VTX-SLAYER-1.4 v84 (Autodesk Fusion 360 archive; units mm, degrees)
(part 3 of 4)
sketch "vtx-antenna_mount" plane through (0, 0, 32) normal (0, 0, -1) x axis (1, 0, 0)
  line L1 (-21.0607, 19.5622) -> (-27.6022, 26.6869)
  curve K1 (-9.6778, 20.9358) -> (-10.9746, 20.0338)
  curve K2 (21.4163, 20.9358) -> (22.7131, 20.0338)
  line L2 (34.4732, 21.3854) -> (32.7992, 19.5622)
  curve K3 (34.4732, 21.3854) -> (34.8613, 29.5821)
  curve K4 (34.4729, 47.5027) -> (34.8613, 50.4161)
  curve K5 (34.8613, 50.4161) -> (34.4732, 58.6128)
  line L3 (32.7992, 60.4361) -> (34.4732, 58.6128)
  curve K6 (21.4163, 59.0625) -> (22.7131, 59.9644)
  curve K7 (-9.6778, 59.0625) -> (-10.9746, 59.9644)
  line L4 (-27.6022, 53.3114) -> (-21.0607, 60.4361)
  line L5 (26.3392, 29.4991) -> (30.319, 29.4991)
  line L6 (30.319, 32.4991) -> (26.3392, 32.4991)
  line L7 (30.319, 50.4991) -> (26.3392, 50.4991)
  line L8 (26.3392, 47.4991) -> (30.319, 47.4991)
  line L9 (30.319, 29.4991) -> (26.3392, 29.4991)
  line L10 (26.3392, 32.4991) -> (30.319, 32.4991)
  line L11 (30.319, 47.4991) -> (26.3392, 47.4991)
  line L12 (26.3392, 50.4991) -> (30.319, 50.4991)
  curve K8 (34.47, 47.4768) -> (31.9524, 44.1894)
  curve K9 (34.4729, 47.5027) -> (34.8613, 50.4161)
  curve K10 (34.8613, 50.4161) -> (34.4732, 58.6128)
  line L13 (34.4732, 58.6128) -> (32.7992, 60.4361)
  curve K11 (22.7131, 59.9644) -> (21.4163, 59.0625)
  curve K12 (34.4732, 21.3854) -> (34.8613, 29.5821)
  line L14 (32.7992, 19.5622) -> (34.4732, 21.3854)
  curve K13 (21.4163, 20.9358) -> (22.7131, 20.0338)
  line L15 (19.3693, 59.1611) -> (19.3693, 25.3947)
  line L16 (42, 39.9991) -> (17.9297, 39.9991)
  line L17 (34.47, 32.5215) -> (34.47, 47.4768)
  line L18 (34.47, 47.4768) -> (34.6901, 56.5235)
  line L19 (34.47, 32.5215) -> (34.6901, 23.4747)
  curve K14 (5.8693, 25.0204) -> (-1.6863, 24.3869)
  curve K15 (5.8693, 54.9778) -> (-1.6863, 55.6114)
  curve K16 (-13.7829, 18.3445) -> (-21.0607, 19.5622)
  curve K17 (-10.9746, 20.0338) -> (-13.7829, 18.3445)
  curve K18 (5.8693, 25.0204) -> (13.4249, 24.3869)
  curve K19 (22.7131, 20.0338) -> (25.5215, 18.3445)
  curve K20 (32.7992, 19.5622) -> (25.5215, 18.3445)
  curve K21 (32.7992, 60.4361) -> (25.5215, 61.6537)
  curve K22 (22.7131, 59.9644) -> (25.5215, 61.6537)
  curve K23 (5.8693, 54.9778) -> (13.4249, 55.6114)
  curve K24 (-10.9746, 59.9644) -> (-13.7829, 61.6537)
  curve K25 (-13.7829, 61.6537) -> (-21.0607, 60.4361)
  curve K26 (-13.7829, 18.3445) -> (-10.9746, 20.0338)
  curve K27 (25.5215, 18.3445) -> (32.7992, 19.5622)
  curve K28 (-9.4692, 21.0728) -> (-9.6778, 20.9358)
  curve K29 (-1.6863, 24.3869) -> (-1.7709, 24.37)
  curve K30 (13.4249, 24.3869) -> (13.5094, 24.37)
  curve K31 (21.2077, 21.0728) -> (21.4163, 20.9358)
  curve K32 (21.2077, 58.9255) -> (21.4163, 59.0625)
  curve K33 (13.4249, 55.6114) -> (13.5094, 55.6283)
  curve K34 (-1.6863, 55.6114) -> (-1.7709, 55.6283)
  curve K35 (-9.4692, 58.9255) -> (-9.6778, 59.0625)
  curve K36 (34.4729, 32.4955) -> (34.8613, 29.5821)
  curve K37 (34.47, 32.5215) -> (31.9524, 35.8089)
  line L20 (24.7082, 44.5019) -> (21.9057, 47.2714)
  line L21 (26.1937, 39.0527) -> (26.1937, 40.9455)
  line L22 (21.9057, 32.7269) -> (24.7082, 35.4963)
  line L23 (2.0745, 29.0204) -> (9.5861, 29.0204)
  line L24 (9.5861, 50.9778) -> (2.0745, 50.9778)
  curve K38 (-1.7709, 24.37) -> (-9.4692, 21.0728)
  curve K39 (13.5094, 24.37) -> (21.2077, 21.0728)
  line L25 (34.4729, 32.4955) -> (34.47, 32.5215)
  line L26 (34.47, 47.4768) -> (34.4729, 47.5027)
  curve K40 (13.5094, 55.6283) -> (21.2077, 58.9255)
  curve K41 (-1.7709, 55.6283) -> (-9.4692, 58.9255)
  line L27 (-9.3955, 28.8599) -> (-15.7249, 35.138)
  line L28 (10.9945, 32.4404) -> (7.2082, 36.196)
  line L29 (4.3798, 36.1845) -> (0.6546, 32.4289)
  line L30 (7.2082, 43.8022) -> (10.9945, 47.5578)
  line L31 (0.6546, 47.5694) -> (4.3798, 43.8137)
  line L32 (-3.666, 33.753) -> (-0.2646, 37.1822)
  line L33 (-12.0826, 37.1592) -> (-8.5664, 33.6715)
  line L34 (-8.5664, 46.3268) -> (-12.0826, 42.839)
  line L35 (-0.2646, 42.816) -> (-3.666, 46.2452)
  line L36 (15.3511, 46.2451) -> (11.9172, 42.839)
  line L37 (11.9172, 37.1592) -> (15.3511, 33.7531)
  line L38 (-15.7249, 44.8602) -> (-9.3955, 51.1383)
  arc A1 centre (-25.3924, 51.2824) radius 3 clockwise from (-26.8824, 48.6786) to (-27.6022, 53.3114)
  arc A2 centre (-31.849, 39.9991) radius 10 clockwise from (-26.8824, 48.6786) to (-26.8824, 31.3197)
  arc A3 centre (-25.3924, 28.7158) radius 3 clockwise from (-27.6022, 26.6869) to (-26.8824, 31.3197)
  circle C1 centre (-18.1307, 23.4991) radius 1.55
  circle C2 centre (-18.1307, 56.4991) radius 1.55
  arc A4 centre (26.3392, 30.9991) radius 1.5 clockwise from (26.3392, 29.4991) to (26.3392, 32.4991)
  arc A5 centre (30.319, 30.9991) radius 1.5 clockwise from (30.319, 32.4991) to (30.319, 29.4991)
  arc A6 centre (30.319, 48.9991) radius 1.5 clockwise from (30.319, 50.4991) to (30.319, 47.4991)
  arc A7 centre (26.3392, 48.9991) radius 1.5 clockwise from (26.3392, 47.4991) to (26.3392, 50.4991)
  arc A8 centre (26.3392, 30.9991) radius 1.5 clockwise from (26.3392, 29.4991) to (26.3392, 32.4991)
  arc A9 centre (30.319, 30.9991) radius 1.5 clockwise from (30.319, 32.4991) to (30.319, 29.4991)
  arc A10 centre (26.3392, 48.9991) radius 1.5 clockwise from (26.3392, 47.4991) to (26.3392, 50.4991)
  arc A11 centre (30.319, 48.9991) radius 1.5 clockwise from (30.319, 50.4991) to (30.319, 47.4991)
  arc A12 centre (33.5931, 39.9991) radius 4.5 clockwise from (31.9524, 35.8089) to (31.9524, 44.1894)
  circle C3 centre (29.8693, 56.4991) radius 4.8209
  circle C4 centre (29.8693, 56.4991) radius 3.025
  circle C5 centre (29.8693, 23.4991) radius 4.8209
  circle C6 centre (29.8693, 23.4991) radius 3.025
  arc A13 centre (50.9984, 39.9992) radius 31.6291 clockwise from (26.0429, 20.5666) to (26.0525, 59.4441)
  circle C7 centre (29.8693, 56.4991) radius 1.55
  circle C8 centre (29.8693, 23.4991) radius 1.55
  circle C9 centre (15.8693, 49.9991) radius 1.05
  circle C10 centre (-4.1307, 49.9991) radius 1.05
  circle C11 centre (15.8693, 29.9991) radius 1.05
  circle C12 centre (-4.1307, 29.9991) radius 1.05
  arc A14 centre (15.8693, 29.9991) radius 3.25 clockwise from (16.4204, 33.202) to (17.9117, 32.5272)
  arc A15 centre (-4.1307, 29.9991) radius 3.25 clockwise from (-5.3387, 33.0163) to (-4.7221, 33.1949)
  arc A16 centre (-18.1307, 23.4991) radius 5.55 clockwise from (-18.4728, 29.0386) to (-13.5782, 26.6736)
  arc A17 centre (-31.849, 39.9991) radius 14 clockwise from (-18.9728, 34.5032) to (-20.2526, 32.1553)
  arc A18 centre (-18.1307, 56.4991) radius 5.55 clockwise from (-13.5782, 53.3246) to (-18.4728, 50.9597)
  arc A19 centre (-4.1307, 49.9991) radius 3.25 clockwise from (-4.7221, 46.8034) to (-5.3387, 46.9819)
  arc A20 centre (15.8693, 49.9991) radius 3.25 clockwise from (17.9117, 47.4711) to (16.4204, 46.7962)
  arc A21 centre (-10.8039, 27.4399) radius 2 clockwise from (-9.3955, 28.8599) to (-10.177, 25.5408)
  arc A22 centre (-11.1174, 28.3895) radius 3 clockwise from (-10.177, 25.5408) to (-13.5782, 26.6736)
  arc A23 centre (-18.596, 31.0348) radius 2 clockwise from (-18.4728, 29.0386) to (-20.2526, 32.1553)
  arc A24 centre (-17.1334, 33.7181) radius 2 clockwise from (-18.9728, 34.5032) to (-15.7249, 35.138)
  arc A25 centre (9.5861, 31.0204) radius 2 clockwise from (10.9945, 32.4404) to (9.5861, 29.0204)
  arc A26 centre (2.0745, 31.0204) radius 2 clockwise from (2.0745, 29.0204) to (0.6546, 32.4289)
  arc A27 centre (5.7998, 34.7761) radius 2 clockwise from (4.3798, 36.1845) to (7.2082, 36.196)
  arc A28 centre (2.0745, 48.9778) radius 2 clockwise from (0.6546, 47.5694) to (2.0745, 50.9778)
  arc A29 centre (9.5861, 48.9778) radius 2 clockwise from (9.5861, 50.9778) to (10.9945, 47.5578)
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  point P53 (34.47, 47.4768)
  point P68 (34.47, 47.4768)
  point P71 (34.6901, 56.5235)
  point P72 (34.47, 47.4768)
  point P75 (34.6901, 23.4747)
  point P76 (34.47, 32.5215)
  point P78 (26.0429, 20.5666)
  point P77 (26.0525, 59.4441)
  perpendicular L15 L16
  coincident P53 P68
  tangent L3 C3
  coincident C3 P71
  coincident P53 P72
  symmetric L16 C3 C5
  symmetric L16 C4 C6
  symmetric L16 P71 P75
  symmetric L16 P72 P76
  tangent L15 A13
  coincident C5 P78
  coincident C3 P77
  dimension "d1057" diameter C4 = 6.05
sketch "turtleFinBase" plane through (0, 0, 33.5) normal (0, 0, 1) x axis (-1, 0, 0)
  line L1 (21.0607, 60.4361) -> (27.6022, 53.3114)
  curve K1 (13.7829, 61.6537) -> (21.0607, 60.4361)
  curve K2 (10.9746, 59.9644) -> (13.7829, 61.6537)
  curve K3 (9.6778, 59.0625) -> (10.9746, 59.9644)
  curve K4 (9.4692, 58.9255) -> (9.6778, 59.0625)
  curve K5 (1.7709, 55.6283) -> (9.4692, 58.9255)
  curve K6 (1.6863, 55.6114) -> (1.7709, 55.6283)
  curve K7 (-5.8693, 54.9778) -> (1.6863, 55.6114)
  curve K8 (-13.4249, 55.6114) -> (-5.8693, 54.9778)
  curve K9 (-13.5094, 55.6283) -> (-13.4249, 55.6114)
  curve K10 (-21.2077, 58.9255) -> (-13.5094, 55.6283)
  curve K11 (-21.4163, 59.0625) -> (-21.2077, 58.9255)
  curve K12 (-22.7131, 59.9644) -> (-21.4163, 59.0625)
  curve K13 (-25.5215, 61.6537) -> (-22.7131, 59.9644)
  curve K14 (-32.7992, 60.4361) -> (-25.5215, 61.6537)
  line L2 (-34.4732, 58.6128) -> (-32.7992, 60.4361)
  curve K15 (-34.8613, 50.4161) -> (-34.4732, 58.6128)
  curve K16 (-34.4729, 47.5027) -> (-34.8613, 50.4161)
  line L3 (-34.47, 47.4768) -> (-34.4729, 47.5027)
  curve K17 (-34.47, 47.4768) -> (-31.9524, 44.1894)
  curve K18 (-31.9524, 35.8089) -> (-34.47, 32.5215)
  line L4 (-34.4729, 32.4955) -> (-34.47, 32.5215)
  curve K19 (-34.8613, 29.5821) -> (-34.4729, 32.4955)
  curve K20 (-34.4732, 21.3854) -> (-34.8613, 29.5821)
  line L5 (-32.7992, 19.5622) -> (-34.4732, 21.3854)
  curve K21 (-25.5215, 18.3445) -> (-32.7992, 19.5622)
  curve K22 (-22.7131, 20.0338) -> (-25.5215, 18.3445)
  curve K23 (-21.4163, 20.9358) -> (-22.7131, 20.0338)
  curve K24 (-21.2077, 21.0728) -> (-21.4163, 20.9358)
  curve K25 (-13.5094, 24.37) -> (-21.2077, 21.0728)
  curve K26 (-13.4249, 24.3869) -> (-13.5094, 24.37)
  curve K27 (-5.8693, 25.0204) -> (-13.4249, 24.3869)
  curve K28 (1.6863, 24.3869) -> (-5.8693, 25.0204)
  curve K29 (1.7709, 24.37) -> (1.6863, 24.3869)
  curve K30 (9.4692, 21.0728) -> (1.7709, 24.37)
  curve K31 (9.6778, 20.9358) -> (9.4692, 21.0728)
  curve K32 (10.9746, 20.0338) -> (9.6778, 20.9358)
  curve K33 (13.7829, 18.3445) -> (10.9746, 20.0338)
  curve K34 (21.0607, 19.5622) -> (13.7829, 18.3445)
  line L6 (27.6022, 26.6869) -> (21.0607, 19.5622)
  line L7 (-15.3511, 33.7531) -> (-11.9172, 37.1592)
  line L8 (-24.7082, 35.4963) -> (-21.9057, 32.7269)
  line L9 (-26.1937, 40.9455) -> (-26.1937, 39.0527)
  line L10 (-21.9057, 47.2714) -> (-24.7082, 44.5019)
  line L11 (-11.9172, 42.839) -> (-15.3511, 46.2451)
  line L12 (-30.319, 29.4991) -> (-26.3392, 29.4991)
  line L13 (-26.3392, 32.4991) -> (-30.319, 32.4991)
  line L14 (-26.3392, 50.4991) -> (-30.319, 50.4991)
  line L15 (-30.319, 47.4991) -> (-26.3392, 47.4991)
  line L16 (-2.0745, 50.9778) -> (-9.5861, 50.9778)
  line L17 (-4.3798, 43.8137) -> (-0.6546, 47.5694)
  line L18 (-10.9945, 47.5578) -> (-7.2082, 43.8022)
  line L19 (15.7249, 35.138) -> (9.3955, 28.8599)
  line L20 (3.666, 46.2452) -> (0.2646, 42.816)
  line L21 (12.0826, 42.839) -> (8.5664, 46.3268)
  line L22 (8.5664, 33.6715) -> (12.0826, 37.1592)
  line L23 (0.2646, 37.1822) -> (3.666, 33.753)
  line L24 (-0.6546, 32.4289) -> (-4.3798, 36.1845)
  line L25 (-9.5861, 29.0204) -> (-2.0745, 29.0204)
  line L26 (-7.2082, 36.196) -> (-10.9945, 32.4404)
  line L27 (9.3955, 51.1383) -> (15.7249, 44.8602)
  line L28 (10.424, 50.6687) -> (18.7336, 51.7161)
  line L29 (8.6626, 58.4333) -> (16.6107, 61.0741)
  line L30 (-20.4518, 21.7537) -> (-28.2425, 18.961)
  line L31 (-22.3854, 29.4762) -> (-30.5729, 28.2684)
  arc A1 centre (25.3924, 51.2824) radius 3 clockwise from (27.6022, 53.3114) to (26.8824, 48.6786)
  arc A2 centre (-33.5931, 39.9991) radius 4.5 clockwise from (-31.9524, 44.1894) to (-31.9524, 35.8089)
  arc A3 centre (25.3924, 28.7158) radius 3 clockwise from (26.8824, 31.3197) to (27.6022, 26.6869)
  arc A4 centre (31.849, 39.9991) radius 10 clockwise from (26.8824, 31.3197) to (26.8824, 48.6786)
  circle C1 centre (-29.8693, 23.4991) radius 1.55
  arc A5 centre (-16.7595, 35.1731) radius 2 clockwise from (-15.3511, 33.7531) to (-16.4204, 33.202)
  arc A6 centre (-15.8693, 29.9991) radius 3.25 clockwise from (-17.9117, 32.5272) to (-16.4204, 33.202)
  arc A7 centre (-19.797, 34.8608) radius 3 clockwise from (-17.9117, 32.5272) to (-21.9057, 32.7269)
  arc A8 centre (-21.1937, 39.0527) radius 5 clockwise from (-24.7082, 35.4963) to (-26.1937, 39.0527)
  arc A9 centre (-21.1937, 40.9455) radius 5 clockwise from (-26.1937, 40.9455) to (-24.7082, 44.5019)
  arc A10 centre (-19.797, 45.1375) radius 3 clockwise from (-21.9057, 47.2714) to (-17.9117, 47.4711)
  arc A11 centre (-15.8693, 49.9991) radius 3.25 clockwise from (-16.4204, 46.7962) to (-17.9117, 47.4711)
  arc A12 centre (-16.7595, 44.8252) radius 2 clockwise from (-16.4204, 46.7962) to (-15.3511, 46.2451)
  arc A13 centre (-14.7341, 39.9991) radius 4 clockwise from (-11.9172, 42.839) to (-11.9172, 37.1592)
  arc A14 centre (-26.3392, 30.9991) radius 1.5 clockwise from (-26.3392, 32.4991) to (-26.3392, 29.4991)
  arc A15 centre (-30.319, 30.9991) radius 1.5 clockwise from (-30.319, 29.4991) to (-30.319, 32.4991)
  circle C2 centre (4.1307, 29.9991) radius 1.05
  circle C3 centre (18.1307, 56.4991) radius 1.55
  circle C4 centre (-15.8693, 49.9991) radius 1.05
  circle C5 centre (18.1307, 23.4991) radius 1.55
  arc A16 centre (-30.319, 48.9991) radius 1.5 clockwise from (-30.319, 47.4991) to (-30.319, 50.4991)
  arc A17 centre (-26.3392, 48.9991) radius 1.5 clockwise from (-26.3392, 50.4991) to (-26.3392, 47.4991)
  circle C6 centre (-29.8693, 56.4991) radius 1.55
  circle C7 centre (-15.8693, 29.9991) radius 1.05
  circle C8 centre (4.1307, 49.9991) radius 1.05
  arc A18 centre (-2.0745, 48.9778) radius 2 clockwise from (-2.0745, 50.9778) to (-0.6546, 47.5694)
  arc A19 centre (-5.7998, 45.2221) radius 2 clockwise from (-4.3798, 43.8137) to (-7.2082, 43.8022)
  arc A20 centre (-9.5861, 48.9778) radius 2 clockwise from (-10.9945, 47.5578) to (-9.5861, 50.9778)
  arc A21 centre (31.849, 39.9991) radius 14 clockwise from (20.2526, 32.1553) to (18.9728, 34.5032)
  arc A22 centre (18.596, 31.0348) radius 2 clockwise from (20.2526, 32.1553) to (18.4728, 29.0386)
  arc A23 centre (18.1307, 23.4991) radius 5.55 clockwise from (13.5782, 26.6736) to (18.4728, 29.0386)
  arc A24 centre (11.1174, 28.3895) radius 3 clockwise from (13.5782, 26.6736) to (10.177, 25.5408)
  arc A25 centre (10.8039, 27.4399) radius 2 clockwise from (10.177, 25.5408) to (9.3955, 28.8599)
  arc A26 centre (17.1334, 33.7181) radius 2 clockwise from (15.7249, 35.138) to (18.9728, 34.5032)
  arc A27 centre (5.0859, 44.8367) radius 2 clockwise from (3.666, 46.2452) to (4.7221, 46.8034)
  arc A28 centre (4.1307, 49.9991) radius 3.25 clockwise from (5.3387, 46.9819) to (4.7221, 46.8034)
  arc A29 centre (6.4537, 44.1968) radius 3 clockwise from (5.3387, 46.9819) to (8.5664, 46.3268)
  arc A30 centre (9.2657, 39.9991) radius 4 clockwise from (12.0826, 42.839) to (12.0826, 37.1592)
  arc A31 centre (6.4537, 35.8014) radius 3 clockwise from (8.5664, 33.6715) to (5.3387, 33.0163)
  arc A32 centre (4.1307, 29.9991) radius 3.25 clockwise from (4.7221, 33.1949) to (5.3387, 33.0163)
  arc A33 centre (5.0859, 35.1615) radius 2 clockwise from (4.7221, 33.1949) to (3.666, 33.753)
  arc A34 centre (3.1045, 39.9991) radius 4 clockwise from (0.2646, 37.1822) to (0.2646, 42.816)
  arc A35 centre (-2.0745, 31.0204) radius 2 clockwise from (-0.6546, 32.4289) to (-2.0745, 29.0204)
  arc A36 centre (-9.5861, 31.0204) radius 2 clockwise from (-9.5861, 29.0204) to (-10.9945, 32.4404)
  arc A37 centre (-5.7998, 34.7761) radius 2 clockwise from (-7.2082, 36.196) to (-4.3798, 36.1845)
  arc A38 centre (31.849, 39.9991) radius 14 clockwise from (18.9728, 45.495) to (20.2526, 47.8429)
  arc A39 centre (17.1334, 46.2801) radius 2 clockwise from (18.9728, 45.495) to (15.7249, 44.8602)
  arc A40 centre (10.8039, 52.5583) radius 2 clockwise from (9.3955, 51.1383) to (10.177, 54.4575)
  arc A41 centre (11.1174, 51.6087) radius 3 clockwise from (10.177, 54.4575) to (13.5782, 53.3246)
  arc A42 centre (18.1307, 56.4991) radius 5.55 clockwise from (18.4728, 50.9597) to (13.5782, 53.3246)
  arc A43 centre (18.596, 48.9635) radius 2 clockwise from (18.4728, 50.9597) to (20.2526, 47.8429)
  circle C9 centre (18.1307, 56.4991) radius 4.8209
  circle C10 centre (-29.8693, 23.4991) radius 4.8209
  circle C11 centre (-21.8016, 25.519) radius 4
  circle C12 centre (9.9238, 54.6373) radius 4
  point P153 (18.7336, 51.7161)
  point P154 (10.424, 50.6687)
  point P155 (16.6107, 61.0741)
  point P156 (8.6626, 58.4333)
  point P157 (-28.2425, 18.961)
  point P158 (-20.4518, 21.7537)
  point P159 (-30.5729, 28.2684)
  point P160 (-22.3854, 29.4762)
  concentric C3 C9
  tangent L1 C9
  concentric C1 C10
  tangent L5 C10
  coincident C9 P153
  coincident C12 P154
  tangent C12 L28
  coincident C9 P155
  coincident C12 P156
  tangent C12 L29
  coincident C10 P157
  coincident C11 P158
  tangent C11 L30
  coincident C10 P159
  coincident C11 P160
  tangent C11 L31
  tangent C9 L29
  tangent C9 L28
  tangent C10 L31
  tangent C10 L30
  dimension "d1172" diameter C11 = 8
  dimension "d1173" diameter C12 = 8
extrude "Extrude141" new body sketch "turtleFinBase" profile of C1 C3 L27 A40 A41 A42 C9 C10 C11 C12 L28 L29 L30 L31 along normal blind 3 bodies "turtleFin"
sketch "Sketch97" plane through (0, 0, 36.5) normal (0, 0, 1) x axis (-1, 0, 0)
  line L1 (8.6626, 58.4333) -> (16.6107, 61.0741)
  line L2 (18.7336, 51.7161) -> (10.424, 50.6687)
  circle C1 centre (18.1307, 56.4991) radius 1.55
  arc A1 centre (18.1307, 56.4991) radius 4.8209 clockwise from (16.6107, 61.0741) to (18.7336, 51.7161)
  arc A2 centre (9.9238, 54.6373) radius 4 clockwise from (10.424, 50.6687) to (8.6626, 58.4333)
  circle C2 centre (9.9238, 54.6373) radius 4
work_plane "WorkPlane19"
sketch "Sketch98" plane through (-9.9238, -54.6373, 33.5) normal (-0.6762, 0.7367, 0) x axis (-0.7367, -0.6762, 0)
  line L1 (-43, 3) -> (0, 3)
  line L2 (-21.5, 38) -> (-21.5, 3)
  line L3 (-4, 0) -> (4, 0)
  line L4 (-47.0624, 0) -> (-39.0624, 0)
  curve K1 (-39.0624, 0) -> (-4, 0)
  curve K2 (-43.0624, 0) -> (0, 0)
  point P4 (-21.5, 3)
  point P7 (-4, 0)
  point P10 (-4, 0)
  point P11 (-21.5, 35.2015)
  point P8 (-39.0624, 0)
  point P12 (-39.0624, 0)
  point P1 (0, 0)
  point P13 (0, 0)
  point P14 (-43.0624, 0)
  point P5 (-21.5, 38)
  horizontal L1
  midpoint L1 P4
  perpendicular L1 L2
  coincident P7 P10
  coincident L2 P11
  coincident P8 P12
  coincident P1 P13
  midpoint L4 P14
  dimension "d1176" distance P4 P5 = 35
sweep "Sweep1" sketch "turtleFinBase" TwistAngle 0 TaperAngle 0
fillet "Fillet113" radius 3
work_plane "WorkPlane15" RotateAngle -45
sketch "vtx-antenna-hole" plane through (20.4594, -39.9991, 30.9099) normal (0.7071, 0, 0.7071) x axis (0, -1, 0)
  line L1 (0, 25) -> (0, -3.5)
  circle C1 centre (0, 11.4101) radius 4.5
  circle C2 centre (0, 11.4101) radius 2.5
  concentric C1 C2
  vertical L1
  dimension "d882" diameter C1 = 9
  dimension "d883" diameter C2 = 5
extrude "Extrude127" new body sketch "vtx-antenna-hole" profile of C1 C2 along normal blind 25 bodies "vtx-antenna-mount"
extrude "Extrude128" add sketch "vtx-antenna_mount" along normal blind 3
extrude "Extrude129" cut sketch "vtx-antenna-hole" profile of C2 along normal blind 47
work_plane "WorkPlane18" RotateAngle -90
sketch "Sketch92" plane through (19.3693, -39.9991, 29) normal (1, 0, 0) x axis (0, 1, 0)
  line L1 (-6.5, 0) -> (6.5, 0)
  line L2 (-6.5, -10.2079) -> (-6.5, 0)
  line L3 (6.5, -10.2079) -> (-6.5, -10.2079)
  line L4 (6.5, 0) -> (6.5, -10.2079)
  line L5 (-8.0736, 0) -> (-19.445, 0)
  line L6 (19.4325, 0) -> (8.0736, 0)
  horizontal L1
  vertical L2
  horizontal L3
  vertical L4
extrude "Extrude130" cut sketch "Sketch92" profile of L1 L2 L3 L4 along normal blind 29
fillet "Fillet99" radius 0.8
fillet "Fillet100" radius 4
fillet "Fillet101" radius 0.7
fillet "Fillet108" radius 3
fillet "Fillet109" radius 7
sketch "Sketch93" plane through (0, 0, 29) normal (0, 0, -1) x axis (1, 0, 0)
  line L1 (26.3392, 47.4991) -> (30.319, 47.4991)
  line L2 (30.319, 50.4991) -> (26.3392, 50.4991)
  line L3 (34.47, 47.4768) -> (34.47, 47.2361)
  line L4 (34.4729, 47.5027) -> (34.47, 47.4768)
  curve K1 (34.8613, 50.4161) -> (34.4729, 47.5027)
  curve K2 (34.4732, 58.6128) -> (34.8613, 50.4161)
  line L5 (33.4204, 59.7595) -> (34.4732, 58.6128)
  line L6 (24.7082, 44.5019) -> (23.7608, 45.4381)
  line L7 (26.1937, 39.0527) -> (26.1937, 40.9455)
  line L8 (23.7609, 34.5602) -> (24.7082, 35.4963)
  line L9 (34.4732, 21.3854) -> (33.4204, 20.2387)
  curve K3 (34.8613, 29.5821) -> (34.4732, 21.3854)
  curve K4 (34.4729, 32.4955) -> (34.8613, 29.5821)
  line L10 (34.47, 32.5215) -> (34.4729, 32.4955)
  line L11 (34.47, 32.7621) -> (34.47, 32.5215)
  line L12 (26.3392, 29.4991) -> (30.319, 29.4991)
  line L13 (30.319, 32.4991) -> (26.3392, 32.4991)
  curve K5 (34.47, 32.7621) -> (36.774, 35.7482)
  curve K6 (36.774, 44.25) -> (34.47, 47.2361)
  arc A1 centre (29.8693, 56.4991) radius 4.8209 clockwise from (26.0525, 59.4441) to (33.4204, 59.7595)
  arc A2 centre (19.5063, 39.9991) radius 7.6719 clockwise from (20.3034, 47.6295) to (20.3035, 32.3688)
  closed curve K7 centre (35.4859, 39.9991)
  arc A3 centre (30.319, 48.9991) radius 1.5 clockwise from (30.319, 50.4991) to (30.319, 47.4991)
  arc A4 centre (26.3392, 48.9991) radius 1.5 clockwise from (26.3392, 47.4991) to (26.3392, 50.4991)
  circle C1 centre (29.8693, 56.4991) radius 3.025
  arc A5 centre (50.9984, 39.9992) radius 31.6291 clockwise from (26.0429, 20.5666) to (22.3382, 26.6202)
  arc A6 centre (21.1937, 40.9455) radius 5 clockwise from (24.7082, 44.5019) to (26.1937, 40.9455)
  arc A7 centre (21.1937, 39.0527) radius 5 clockwise from (26.1937, 39.0527) to (24.7082, 35.4963)
  arc A8 centre (29.8693, 23.4991) radius 4.8209 clockwise from (33.4204, 20.2387) to (26.0429, 20.5666)
  closed curve K8 centre (34.6859, 39.9991)
  circle C2 centre (29.8693, 23.4991) radius 3.025
  arc A9 centre (30.319, 30.9991) radius 1.5 clockwise from (30.319, 32.4991) to (30.319, 29.4991)
  arc A10 centre (26.3392, 30.9991) radius 1.5 clockwise from (26.3392, 29.4991) to (26.3392, 32.4991)
  arc A11 centre (28.6812, 29.5812) radius 7 clockwise from (22.3382, 26.6202) to (23.7609, 34.5602)
  arc A12 centre (50.9984, 39.9992) radius 31.6291 clockwise from (22.3382, 53.3781) to (26.0525, 59.4441)
  arc A13 centre (28.6811, 50.4171) radius 7 clockwise from (23.7608, 45.4381) to (22.3382, 53.3781)
sketch "25.6 mount" plane through (0, 0, 7) normal (0, 0, 1) x axis (-1, 0, 0)
  curve K1 (2.0117, 48.6726) -> (-5.8693, 49.9885)
  curve K2 (11.053, 39.9991) -> (5.0002, 47.6552)
  curve K3 (5.0002, 32.3431) -> (11.053, 39.9991)
  curve K4 (-5.8693, 30.0098) -> (2.0117, 31.3257)
  curve K5 (-13.7502, 31.3257) -> (-5.8693, 30.0098)
  curve K6 (-15.8119, 47.4998) -> (-15.9266, 32.4985)
  curve K7 (-5.8693, 49.9885) -> (-13.7502, 48.6726)
  curve K8 (-34.4732, 21.3854) -> (-34.8613, 29.5821)
  line L1 (-32.7992, 19.5622) -> (-34.4732, 21.3854)
  curve K9 (-32.7992, 19.5622) -> (-25.5215, 18.3445)
  curve K10 (-22.7131, 20.0338) -> (-25.5215, 18.3445)
  curve K11 (-21.4163, 20.9358) -> (-22.7131, 20.0338)
  curve K12 (-21.2077, 21.0728) -> (-21.4163, 20.9358)
  curve K13 (-13.5094, 24.37) -> (-21.2077, 21.0728)
  curve K14 (-13.4249, 24.3869) -> (-13.5094, 24.37)
  curve K15 (-5.8693, 25.0204) -> (-13.4249, 24.3869)
  curve K16 (-5.8693, 25.0204) -> (1.6863, 24.3869)
  curve K17 (1.6863, 24.3869) -> (1.7709, 24.37)
  curve K18 (9.4692, 21.0728) -> (1.7709, 24.37)
  curve K19 (9.4692, 21.0728) -> (9.6778, 20.9358)
  curve K20 (9.6778, 20.9358) -> (10.9746, 20.0338)
  curve K21 (10.9746, 20.0338) -> (13.7829, 18.3445)
  curve K22 (13.7829, 18.3445) -> (21.0607, 19.5622)
  line L2 (21.7601, 20.324) -> (21.0607, 19.5622)
  curve K23 (23.3399, 24.4614) -> (21.2218, 28.4813)
  curve K24 (14.991, 38.4401) -> (21.2218, 28.4813)
  curve K25 (14.9178, 39.9991) -> (14.991, 38.4401)
  curve K26 (14.9178, 39.9991) -> (14.991, 41.5582)
  curve K27 (14.991, 41.5582) -> (21.2218, 51.5169)
  curve K28 (21.2218, 51.5169) -> (23.3399, 55.5369)
  line L3 (21.0607, 60.4361) -> (21.7601, 59.6743)
  curve K29 (13.7829, 61.6537) -> (21.0607, 60.4361)
  curve K30 (10.9746, 59.9644) -> (13.7829, 61.6537)
  curve K31 (9.6778, 59.0625) -> (10.9746, 59.9644)
  curve K32 (9.4692, 58.9255) -> (9.6778, 59.0625)
  curve K33 (1.7709, 55.6283) -> (9.4692, 58.9255)
  curve K34 (1.6863, 55.6114) -> (1.7709, 55.6283)
  curve K35 (-5.8693, 54.9778) -> (1.6863, 55.6114)
  curve K36 (-5.8693, 54.9778) -> (-13.4249, 55.6114)
  curve K37 (-13.4249, 55.6114) -> (-13.5094, 55.6283)
  curve K38 (-21.2077, 58.9255) -> (-13.5094, 55.6283)
  curve K39 (-21.2077, 58.9255) -> (-21.4163, 59.0625)
  curve K40 (-21.4163, 59.0625) -> (-22.7131, 59.9644)
  curve K41 (-22.7131, 59.9644) -> (-25.5215, 61.6537)
  curve K42 (-32.7992, 60.4361) -> (-25.5215, 61.6537)
  line L4 (-34.4732, 58.6128) -> (-32.7992, 60.4361)
  curve K43 (-34.8613, 50.4161) -> (-34.4732, 58.6128)
  curve K44 (-34.4729, 47.5027) -> (-34.8613, 50.4161)
  curve K45 (-34.2161, 44.4991) -> (-34.4729, 47.5027)
  curve K46 (-34.0919, 41.4991) -> (-34.2161, 44.4991)
  curve K47 (-34.0692, 39.9991) -> (-34.0919, 41.4991)
  curve K48 (-34.0919, 38.4991) -> (-34.0692, 39.9991)
  curve K49 (-34.0919, 38.4991) -> (-34.2161, 35.4991)
  curve K50 (-34.4729, 32.4955) -> (-34.2161, 35.4991)
  curve K51 (-34.4729, 32.4955) -> (-34.8613, 29.5821)
  line L5 (-26.3392, 32.4991) -> (-30.319, 32.4991)
  line L6 (-30.319, 29.4991) -> (-26.3392, 29.4991)
  line L7 (-23.7522, 38.4991) -> (-30.319, 38.4991)
  line L8 (-30.319, 35.4991) -> (-23.7522, 35.4991)
  line L9 (-26.3392, 50.4991) -> (-30.319, 50.4991)
  line L10 (-30.319, 47.4991) -> (-26.3392, 47.4991)
  line L11 (-23.7522, 44.4991) -> (-30.319, 44.4991)
  line L12 (-30.319, 41.4991) -> (-23.7522, 41.4991)
  line L13 (-15.8693, 49.9991) -> (4.1307, 29.9991)
  line L14 (-15.8693, 29.9991) -> (4.1307, 49.9991)
  line L15 (-5.8693, 9.9991) -> (-5.8693, 39.9991)
  line L16 (-35.8693, 39.9991) -> (-5.8693, 39.9991)
  line L17 (-5.8693, 69.9991) -> (-5.8693, 39.9991)
  line L18 (24.1307, 39.9991) -> (-5.8693, 39.9991)
  line L19 (-23.9712, 39.9991) -> (-5.8693, 58.1011)
  line L20 (-5.8693, 21.8972) -> (-23.9712, 39.9991)
  line L21 (-5.8693, 21.8972) -> (12.2327, 39.9991)
  line L22 (0.3923, 24.6107) -> (-4.104, 20.127)
  line L23 (-12.109, 24.6139) -> (-7.6395, 20.1319)
  line L24 (0.3923, 55.3876) -> (-4.104, 59.8713)
  line L25 (-12.109, 55.3843) -> (-7.6395, 59.8663)
  arc A1 centre (4.1307, 49.9991) radius 2.5 clockwise from (5.0002, 47.6552) to (2.0117, 48.6726)
  arc A2 centre (4.1307, 29.9991) radius 2.5 clockwise from (2.0117, 31.3257) to (5.0002, 32.3431)
  arc A3 centre (-15.8693, 29.9991) radius 2.5 clockwise from (-15.9266, 32.4985) to (-13.7502, 31.3257)
  arc A4 centre (-15.8693, 49.9991) radius 2.5 clockwise from (-13.7502, 48.6726) to (-15.8119, 47.4998)
  arc A5 centre (17.3404, 24.3819) radius 6 clockwise from (23.3399, 24.4614) to (21.7601, 20.324)
  arc A6 centre (17.3404, 55.6164) radius 6 clockwise from (21.7601, 59.6743) to (23.3399, 55.5369)
  arc A7 centre (-30.319, 30.9991) radius 1.5 clockwise from (-30.319, 29.4991) to (-30.319, 32.4991)
  arc A8 centre (-26.3392, 30.9991) radius 1.5 clockwise from (-26.3392, 32.4991) to (-26.3392, 29.4991)
  arc A9 centre (-23.7522, 36.9991) radius 1.5 clockwise from (-23.7522, 38.4991) to (-23.7522, 35.4991)
  arc A10 centre (-30.319, 36.9991) radius 1.5 clockwise from (-30.319, 35.4991) to (-30.319, 38.4991)
  arc A11 centre (-26.3392, 48.9991) radius 1.5 clockwise from (-26.3392, 50.4991) to (-26.3392, 47.4991)
  arc A12 centre (-30.319, 48.9991) radius 1.5 clockwise from (-30.319, 47.4991) to (-30.319, 50.4991)
  circle C1 centre (-29.8693, 56.4991) radius 2.55
  circle C2 centre (18.1307, 56.4991) radius 2.55
  circle C3 centre (-29.8693, 23.4991) radius 2.55
  circle C4 centre (18.1307, 23.4991) radius 2.55
  circle C5 centre (4.1307, 49.9991) radius 1.05
  circle C6 centre (-15.8693, 49.9991) radius 1.05
  circle C7 centre (4.1307, 29.9991) radius 1.05
  circle C8 centre (-15.8693, 29.9991) radius 1.05
  arc A13 centre (-30.319, 42.9991) radius 1.5 clockwise from (-30.319, 41.4991) to (-30.319, 44.4991)
  arc A14 centre (-23.7522, 42.9991) radius 1.5 clockwise from (-23.7522, 44.4991) to (-23.7522, 41.4991)
  circle C9 centre (-5.8693, 21.8972) radius 1.05
  circle C10 centre (-5.8693, 58.1011) radius 1.05
  circle C11 centre (12.2327, 39.9991) radius 1.05
  circle C12 centre (-23.9712, 39.9991) radius 1.05
  circle C13 centre (-5.8693, 21.8972) radius 2.5
  circle C14 centre (-5.8693, 58.1011) radius 2.5
  circle C15 centre (12.2327, 39.9991) radius 4
  circle C16 centre (-23.9712, 39.9991) radius 4
  circle C17 centre (-28.581, 42.9991) radius 1.5
  circle C18 centre (-28.581, 36.9991) radius 1.5
  point P9 (4.1307, 29.9991)
  point P97 (4.1307, 29.9991)
  point P16 (-15.8693, 49.9991)
  point P98 (-15.8693, 49.9991)
  point P5 (4.1307, 49.9991)
  point P99 (4.1307, 49.9991)
  point P13 (-15.8693, 29.9991)
  point P100 (-15.8693, 29.9991)
  point P101 (-5.8693, 39.9991)
  point P106 (-5.8693, 21.8972)
  point P107 (-5.8693, 58.1011)
  point P108 (12.2327, 39.9991)
  point P109 (-23.9712, 39.9991)
  point P110 (-5.8693, 58.1011)
  point P111 (-23.9712, 39.9991)
  point P112 (-23.9712, 39.9991)
  point P113 (-5.8693, 21.8972)
  point P114 (12.2327, 39.9991)
  point P115 (-5.8693, 21.8972)
  point P118 (-23.9712, 39.9991)
  point P121 (-4.104, 20.127)
  point P122 (0.3923, 24.6107)
  point P123 (-7.6395, 20.1319)
  point P124 (-12.109, 24.6139)
  point P125 (-4.104, 59.8713)
  point P126 (0.3923, 55.3876)
  point P127 (-7.6395, 59.8663)
  point P128 (-12.109, 55.3843)
  point P119 (-28.581, 42.9991)
  point P120 (-28.581, 36.9991)
  coincident P9 P97
  coincident P16 P98
  coincident P5 P99
  coincident P13 P100
  midpoint L14 P101
  vertical L15
  perpendicular L15 L16
  perpendicular L16 L17
  perpendicular L15 L18
  coincident L15 P106
  coincident L17 P107
  coincident L18 P108
  coincident L16 P109
  coincident P107 P110
  coincident P109 P111
  coincident P109 P112
  coincident P106 P113
  coincident P108 P114
  coincident P113 P115
  concentric C10 C14
  concentric C11 C15
  coincident P111 P118
  tangent L11 C17
  tangent L8 C18
  coincident C13 P121
  coincident K16 P122
  tangent C13 L22
  coincident C13 P123
  coincident K15 P124
  tangent C13 L23
  perpendicular L22 L23
  symmetric L16 P121 P125
  symmetric L16 P122 P126
  symmetric L16 P123 P127
  symmetric L16 P124 P128
  tangent L7 C18
  tangent L12 C17
  vertical P119 P120
  tangent C16 C18
  dimension "d1130" diameter C9 = 2.1
  dimension "d1131" diameter C10 = 2.1
  dimension "d1132" diameter C11 = 2.1
  dimension "d1133" diameter C12 = 2.1
  dimension "d1138" distance P107 P109 = 25.6
  dimension "d1139" angle L17 L19 = 45
  dimension "d1140" distance P106 P109 = 25.6
  dimension "d1141" distance P113 P114 = 25.6
  dimension "d1142" diameter C13 = 5
  dimension "d1143" diameter C14 = 5
  dimension "d1144" diameter C15 = 8
  dimension "d1145" diameter C16 = 8
extrude "Extrude133" cut sketch "25.6 mount" profile of C11 C12 against normal blind 6
extrude "Extrude134" add sketch "25.6 mount" profile of K2 K3 K15 K16 K24 K25 K26 K27 K35 K36 L7 A9 L8 L11 A14 L12 C9 C10 C13 C14 C15 C16 C17 C18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 against normal blind 2
extrude "Extrude135" cut sketch "25.6 mount" profile of C11 C12 against normal blind 2
fillet "Fillet110" radius 3
extrude "Extrude136" cut sketch "25.6 mount" profile of C11 C12 against normal blind 12
sketch "Sketch95" plane through (0, 0, -2) normal (0, 0, -1) x axis (1, 0, 0)
  curve K1 (32.9603, 51.5169) -> (35.0785, 55.5369)
  line L1 (32.7992, 60.4361) -> (33.4986, 59.6743)
  curve K2 (32.7992, 60.4361) -> (25.5215, 61.6537)
  curve K3 (22.7131, 59.9644) -> (25.5215, 61.6537)
  curve K4 (21.4163, 59.0625) -> (22.7131, 59.9644)
  curve K5 (13.5094, 55.6283) -> (21.4163, 59.0625)
  curve K6 (13.4249, 55.6114) -> (13.5094, 55.6283)
  curve K7 (5.8693, 54.9778) -> (13.4249, 55.6114)
  curve K8 (-1.6863, 55.6114) -> (5.8693, 54.9778)
  curve K9 (-1.7709, 55.6283) -> (-1.6863, 55.6114)
  curve K10 (-9.6778, 59.0625) -> (-1.7709, 55.6283)
  curve K11 (-10.9746, 59.9644) -> (-9.6778, 59.0625)
  curve K12 (-13.7829, 61.6537) -> (-10.9746, 59.9644)
  curve K13 (-13.7829, 61.6537) -> (-21.0607, 60.4361)
  line L2 (-32.5504, 47.922) -> (-21.0607, 60.4361)
  line L3 (-34.1307, 36.1341) -> (-34.1307, 43.8641)
  line L4 (-21.0607, 19.5622) -> (-32.5504, 32.0762)
  curve K14 (-13.7829, 18.3445) -> (-21.0607, 19.5622)
  curve K15 (-13.7829, 18.3445) -> (-10.9746, 20.0338)
  curve K16 (-10.9746, 20.0338) -> (-9.6778, 20.9358)
  curve K17 (-9.6778, 20.9358) -> (-1.7709, 24.37)
  curve K18 (-1.7709, 24.37) -> (-1.6863, 24.3869)
  curve K19 (-1.6863, 24.3869) -> (5.8693, 25.0204)
  curve K20 (5.8693, 25.0204) -> (13.4249, 24.3869)
  curve K21 (13.4249, 24.3869) -> (13.5094, 24.37)
  curve K22 (13.5094, 24.37) -> (21.4163, 20.9358)
  curve K23 (21.4163, 20.9358) -> (22.7131, 20.0338)
  curve K24 (22.7131, 20.0338) -> (25.5215, 18.3445)
  curve K25 (32.7992, 19.5622) -> (25.5215, 18.3445)
  line L5 (33.4986, 20.324) -> (32.7992, 19.5622)
  curve K26 (35.0785, 24.4614) -> (32.9603, 28.4813)
  curve K27 (32.9603, 28.4813) -> (26.7295, 38.4401)
  curve K28 (26.7295, 38.4401) -> (26.6564, 39.9991)
  curve K29 (26.7295, 41.5582) -> (26.6564, 39.9991)
  curve K30 (32.9603, 51.5169) -> (26.7295, 41.5582)
  line L6 (-14.6007, 32.4991) -> (-25.1307, 32.4991)
  line L7 (-25.1307, 29.4991) -> (-14.6007, 29.4991)
  line L8 (-29.6307, 35.4991) -> (-12.0137, 35.4991)
  line L9 (-12.0137, 38.4991) -> (-29.6307, 38.4991)
  line L10 (-12.0137, 44.4991) -> (-29.6307, 44.4991)
  line L11 (-29.6307, 41.4991) -> (-12.0137, 41.4991)
  line L12 (-25.1307, 47.4991) -> (-14.6007, 47.4991)
  line L13 (-14.6007, 50.4991) -> (-25.1307, 50.4991)
  circle C1 centre (23.9712, 39.9991) radius 1.05
  circle C2 centre (-12.2327, 39.9991) radius 1.05
  arc A1 centre (29.079, 55.6164) radius 6 clockwise from (33.4986, 59.6743) to (35.0785, 55.5369)
  arc A2 centre (-28.1307, 43.8641) radius 6 clockwise from (-34.1307, 43.8641) to (-32.5504, 47.922)
  arc A3 centre (-28.1307, 36.1341) radius 6 clockwise from (-32.5504, 32.0762) to (-34.1307, 36.1341)
  arc A4 centre (29.079, 24.3819) radius 6 clockwise from (35.0785, 24.4614) to (33.4986, 20.324)
  circle C3 centre (29.8693, 23.4991) radius 1.55
  arc A5 centre (15.8693, 29.9991) radius 2.1 clockwise from (15.8711, 32.0991) to (15.8711, 27.8991)
  arc A6 centre (15.873, 29.9991) radius 2.1 clockwise from (15.8711, 27.8991) to (15.8711, 32.0991)
  circle C4 centre (-4.1307, 29.9991) radius 2.1
  circle C5 centre (-18.1307, 23.4991) radius 1.55
  arc A7 centre (-14.6007, 30.9991) radius 1.5 clockwise from (-14.6007, 32.4991) to (-14.6007, 29.4991)
  arc A8 centre (-25.1307, 30.9991) radius 1.5 clockwise from (-25.1307, 29.4991) to (-25.1307, 32.4991)
  arc A9 centre (-29.6307, 36.9991) radius 1.5 clockwise from (-29.6307, 35.4991) to (-29.6307, 38.4991)
  arc A10 centre (-12.0137, 36.9991) radius 1.5 clockwise from (-12.0137, 38.4991) to (-12.0137, 35.4991)
  circle C6 centre (5.8693, 39.9991) radius 3
  arc A11 centre (-12.0137, 42.9991) radius 1.5 clockwise from (-12.0137, 44.4991) to (-12.0137, 41.4991)
  arc A12 centre (-29.6307, 42.9991) radius 1.5 clockwise from (-29.6307, 41.4991) to (-29.6307, 44.4991)
  arc A13 centre (-25.1307, 48.9991) radius 1.5 clockwise from (-25.1307, 47.4991) to (-25.1307, 50.4991)
  arc A14 centre (-14.6007, 48.9991) radius 1.5 clockwise from (-14.6007, 50.4991) to (-14.6007, 47.4991)
  circle C7 centre (-18.1307, 56.4991) radius 1.55
  circle C8 centre (-4.1307, 49.9991) radius 2.1
  arc A15 centre (15.8693, 49.9991) radius 2.1 clockwise from (15.8711, 52.0991) to (15.8711, 47.8991)
  arc A16 centre (15.873, 49.9991) radius 2.1 clockwise from (15.8711, 47.8991) to (15.8711, 52.0991)
  circle C9 centre (29.8693, 56.4991) radius 1.55
  circle C10 centre (-12.2327, 39.9991) radius 2.1
  circle C11 centre (23.9712, 39.9991) radius 2.1
  circle C12 centre (-12.2327, 39.9991) radius 4
  circle C13 centre (23.9712, 39.9991) radius 4
  circle C14 centre (-16.8424, 42.9991) radius 1.5
  circle C15 centre (-16.8424, 36.9991) radius 1.5
  concentric C2 C10
  concentric C1 C11
  concentric C2 C12
  concentric C11 C13
  tangent L10 C14
  tangent L11 C14
  tangent C12 C14
  tangent L9 C15
  tangent L8 C15
  tangent C12 C15
  dimension "d1156" diameter C10 = 4.2
  dimension "d1157" diameter C11 = 4.2
  dimension "d1158" diameter C12 = 8
  dimension "d1159" diameter C13 = 8
extrude "Extrude137" add sketch "Sketch95" profile of K27 K28 K29 K30 L8 L9 A10 L10 A11 L11 C10 C12 C13 C14 C15 against normal blind 2
extrude "Extrude138" cut sketch "Sketch95" profile of C1 C2 L9 A10 A11 L11 C10 C11 against normal blind 2
fillet "Fillet111" radius 3
extrude "Extrude139" add sketch "25.6 mount" profile of K2 K3 K24 K25 K26 K27 L7 A9 A14 L12 C11 C12 C15 C16 against normal blind 4
extrude "Extrude140" cut sketch "25.6 mount" profile of K2 K3 K24 K25 K26 K27 L7 A9 A14 L12 C11 C12 C15 C16 against normal blind 2
fillet "Fillet112" radius 3
component_insert "Component Insert5"
component_insert "Component Insert6"
extrude "Extrude132" new body sketch "cam-mount-base" profile of C2 C4 along normal blind 25 bodies "standoff1", "standoff2"
copy_paste_bodies "CopyPasteBodies13"
move "Move24"
component_insert "Component Insert7"
joint "Assemble6" alignAngle 0 alignOffsetX 0 alignOffsetY 0 alignOffsetZ 0
component_insert "Component Insert8"
component_insert "Component Insert9"
component_insert "Component Insert10"
joint "Assemble9" alignAngle 0 alignOffsetX 0 alignOffsetY 0 alignOffsetZ 0
component_insert "Component Insert11"
component_insert "Component Insert12"
component_insert "Component Insert13"
component_insert "Component Insert14"
component_insert "Component Insert15"
joint "Assemble14" alignAngle 0 alignOffsetX 0 alignOffsetY 0 alignOffsetZ 0
component_insert "Component Insert16"
component_insert "Component Insert17"
component_insert "Component Insert18"
joint "Assemble15" alignAngle 0 alignOffsetX 0 alignOffsetY 0 alignOffsetZ 0
joint "Assemble16" alignAngle 0 alignOffsetX 0 alignOffsetY 0 alignOffsetZ 0
joint "Assemble17" alignAngle 0 alignOffsetX 0 alignOffsetY 0 alignOffsetZ 0
component_insert "Component Insert19"
component_insert "Component Insert20"
joint "Assemble18" alignAngle 0 alignOffsetX 0 alignOffsetY 0 alignOffsetZ 0
joint "Assemble19" alignAngle 0 alignOffsetX 0 alignOffsetY 0 alignOffsetZ 0
component_insert "Component Insert21"
component_insert "Component Insert22"
joint "Assemble20" alignAngle 0 alignOffsetX 0 alignOffsetY 0 alignOffsetZ 0
joint "Assemble21" alignAngle 0 alignOffsetX 0 alignOffsetY 0 alignOffsetZ 0
component_insert "Component Insert23"
component_insert "Component Insert24"
component_insert "Component Insert25"
component_insert "Component Insert26"
joint "Assemble22" alignAngle 0 alignOffsetX 0 alignOffsetY 0 alignOffsetZ 0
joint "Assemble23" alignAngle 0 alignOffsetX 0 alignOffsetY 0 alignOffsetZ 0
joint "Assemble24" alignAngle 0 alignOffsetX 0 alignOffsetY 0 alignOffsetZ 0
joint "Assemble25" alignAngle 0 alignOffsetX 0 alignOffsetY 0 alignOffsetZ 0
component_insert "Component Insert27"
component_insert "Component Insert28"
component_insert "Component Insert29"
joint "Assemble26" alignAngle 0 alignOffsetX 0 alignOffsetY 0 alignOffsetZ 0
joint "Assemble27" alignAngle 0 alignOffsetX 0 alignOffsetY 0 alignOffsetZ 0
joint "Assemble28" alignAngle 0 alignOffsetX 0 alignOffsetY 0 alignOffsetZ 0
joint "Assemble29" alignAngle 0 alignOffsetX 0 alignOffsetY 0 alignOffsetZ 0
joint "Assemble30" alignAngle 0 alignOffsetX 0 alignOffsetY 0 alignOffsetZ 0
joint "Assemble31" alignAngle 0 alignOffsetX 0 alignOffsetY 0 alignOffsetZ 0
joint "Assemble32" alignAngle 0 alignOffsetX 0 alignOffsetY 0 alignOffsetZ 0
component_from_bodies "Body->Comp11"
component_from_bodies "Body->Comp12"
component_from_bodies "Body->Comp13"
component_from_bodies "Body->Comp14"
component_from_bodies "Body->Comp15"
component_from_bodies "Body->Comp16"
component_from_bodies "Body->Comp17"
component_from_bodies "Body->Comp18"
component_from_bodies "Body->Comp19"
component_from_bodies "Body->Comp21"
component_from_bodies "Body->Comp22"
component_from_bodies "Body->Comp23"
component_from_bodies "Body->Comp24"
sketch "pressnut1" plane through (0, 0, 5.9) normal (0, 0, 1) x axis (-1, 0, 0)
  circle C1 centre (-29.8693, 23.4991) radius 1.55
  circle C2 centre (-29.8693, 23.4991) radius 2.25
extrude "Extrude124" new body sketch "pressnut1" along normal blind 0.7 bodies "pressnut1"
sketch "pressnut2" plane through (0, 0, 6.6) normal (0, 0, 1) x axis (-1, 0, 0)
  line L1 (-29.6425, 21.2606) -> (-29.8656, 20.8741)
  line L2 (-29.4194, 20.8741) -> (-29.8656, 20.8741)
  line L3 (-30.0883, 21.2598) -> (-29.8656, 20.8741)
  line L4 (-29.1966, 21.352) -> (-29.3373, 20.9286)
  line L5 (-29.6331, 21.2615) -> (-29.3373, 20.9286)
  line L6 (-28.7781, 21.5314) -> (-28.8308, 21.0883)
  line L7 (-29.1875, 21.3549) -> (-28.8308, 21.0883)
  line L8 (-28.4044, 21.7913) -> (-28.3667, 21.3467)
  line L9 (-28.7698, 21.536) -> (-28.3667, 21.3467)
  line L10 (-28.0906, 22.1212) -> (-27.9642, 21.6932)
  line L11 (-28.3972, 21.7975) -> (-27.9642, 21.6932)
  line L12 (-27.8496, 22.5074) -> (-27.6397, 22.1137)
  line L13 (-28.0848, 22.1287) -> (-27.6397, 22.1137)
  line L14 (-27.6913, 22.9343) -> (-27.4064, 22.5908)
  line L15 (-27.8454, 22.516) -> (-27.4064, 22.5908)
  line L16 (-27.6222, 23.3843) -> (-27.274, 23.1052)
  line L17 (-27.6889, 22.9435) -> (-27.274, 23.1052)
  line L18 (-27.6451, 23.8389) -> (-27.2478, 23.6357)
  line L19 (-27.6217, 23.3938) -> (-27.2478, 23.6357)
  line L20 (-27.759, 24.2797) -> (-27.329, 24.1606)
  line L21 (-27.6465, 23.8483) -> (-27.329, 24.1606)
  line L22 (-27.9593, 24.6885) -> (-27.5141, 24.6584)
  line L23 (-27.7623, 24.2886) -> (-27.5141, 24.6584)
  line L24 (-28.2379, 25.0486) -> (-27.7957, 25.1088)
  line L25 (-27.9644, 24.6966) -> (-27.7957, 25.1088)
  line L26 (-28.5832, 25.3453) -> (-28.1622, 25.4932)
  line L27 (-28.2444, 25.0555) -> (-28.1622, 25.4932)
  line L28 (-28.9811, 25.5664) -> (-28.5985, 25.796)
  line L29 (-28.591, 25.3507) -> (-28.5985, 25.796)
  line L30 (-29.4155, 25.7029) -> (-29.0869, 26.0048)
  line L31 (-28.9899, 25.5702) -> (-29.0869, 26.0048)
  line L32 (-29.8684, 25.7491) -> (-29.6073, 26.111)
  line L33 (-29.4248, 25.7048) -> (-29.6073, 26.111)
  line L34 (-30.3213, 25.7032) -> (-30.1384, 26.1103)
  line L35 (-29.8779, 25.7491) -> (-30.1384, 26.1103)
  line L36 (-30.7557, 25.5671) -> (-30.6585, 26.0026)
  line L37 (-30.3306, 25.7013) -> (-30.6585, 26.0026)
  line L38 (-31.1539, 25.3463) -> (-31.1463, 25.7925)
  line L39 (-30.7645, 25.5634) -> (-31.1463, 25.7925)
  line L40 (-31.4994, 25.0499) -> (-31.5819, 25.4885)
  line L41 (-31.1617, 25.3409) -> (-31.5819, 25.4885)
  line L42 (-31.7782, 24.69) -> (-31.9473, 25.103)
  line L43 (-31.506, 25.043) -> (-31.9473, 25.103)
  line L44 (-31.9789, 24.2814) -> (-32.2276, 24.6519)
  line L45 (-31.7833, 24.682) -> (-32.2276, 24.6519)
  line L46 (-32.0932, 23.8407) -> (-32.4114, 24.1536)
  line L47 (-31.9822, 24.2725) -> (-32.4114, 24.1536)
  line L48 (-32.1164, 23.3861) -> (-32.4911, 23.6285)
  line L49 (-32.0946, 23.8313) -> (-32.4911, 23.6285)
  line L50 (-32.0477, 22.936) -> (-32.4634, 23.098)
  line L51 (-32.1159, 23.3766) -> (-32.4634, 23.098)
  line L52 (-31.8897, 22.509) -> (-32.3296, 22.5841)
  line L53 (-32.0453, 22.9268) -> (-32.3296, 22.5841)
  line L54 (-31.6491, 22.1226) -> (-32.095, 22.1075)
  line L55 (-31.8855, 22.5005) -> (-32.095, 22.1075)
  line L56 (-31.3355, 21.7925) -> (-31.7694, 21.688)
  line L57 (-31.6432, 22.1151) -> (-31.7694, 21.688)
  line L58 (-30.962, 21.5323) -> (-31.3659, 21.3425)
  line L59 (-31.3283, 21.7863) -> (-31.3659, 21.3425)
  line L60 (-30.5437, 21.3526) -> (-30.9011, 21.0854)
  line L61 (-30.9537, 21.5277) -> (-30.9011, 21.0854)
  line L62 (-30.0978, 21.2608) -> (-30.3941, 20.9271)
  line L63 (-30.5346, 21.3497) -> (-30.3941, 20.9271)
  circle C1 centre (-29.8693, 23.4991) radius 1.55
  circle C2 centre (-29.8693, 23.4991) radius 2.25
  circle C3 centre (-29.8693, 23.4991) radius 2.625
  point P4 (-29.8656, 20.8741)
  point P5 (-29.6425, 21.2606)
  point P7 (-30.0883, 21.2598)
  concentric C1 C3
  horizontal L2
  coincident C3 P4
  coincident C2 P5
  coincident C2 P7
  dimension "d1044" diameter C3 = 5.25 (= "4.500 mm + 0.75 mm")
  dimension "d1045" angle L1 L2 = 60
  dimension "d1046" angle L1 L3 = 60
  dimension "d1048" C-Pattern1-Angle = 360
extrude "Extrude125" add sketch "pressnut2" profile of C1 C2 L1 L3 L4 L5 L6 L7 L8 L9 L10 L11 L12 L13 L14 L15 L16 L17 L18 L19 L20 L21 L22 L23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 along normal blind 0.4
